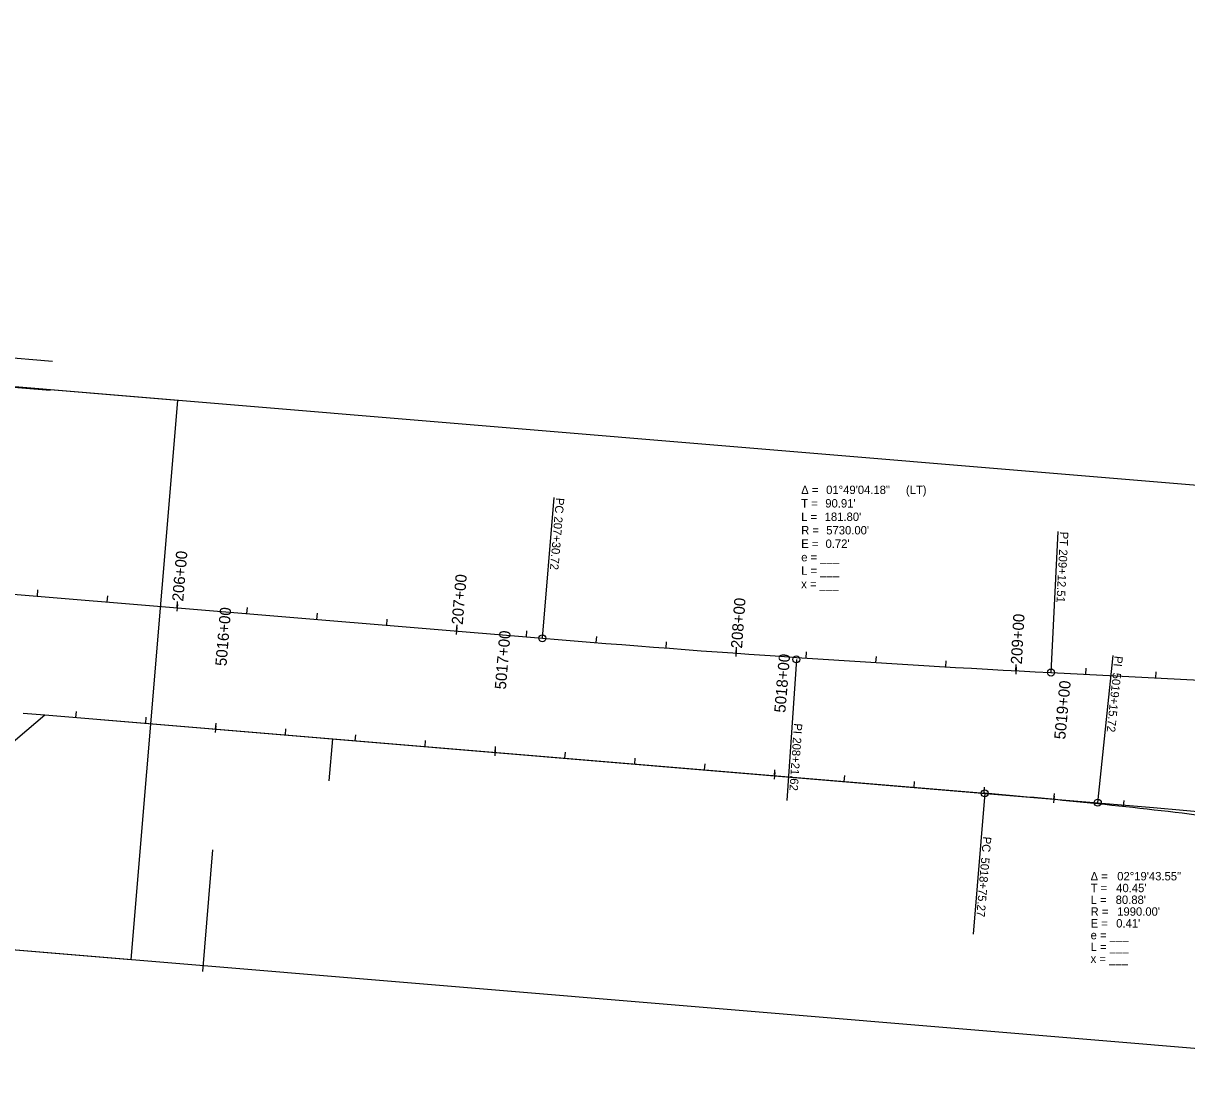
# Model space of a CAD drawing. Extents: x 20500393 to 20505339, y 7953466 to 7954298.
# Drawn here: x 20504244.5 to 20504659.4, y 7953509.6 to 7953886.7 of the extents above; entities that cross this region are included whole.
import ezdxf

# ---------------------------------------------------------------- set-up
doc = ezdxf.new("R2010")
doc.units = 0
for name, color, linetype in [('_CIVIL_CONSTRUCTION', 7, 'Continuous'), ('Alignment', 7, 'Continuous'), ('Draft_2', 7, 'Continuous'), ('Draft_3', 7, 'Continuous'), ('Draft_7', 7, 'Continuous'), ('NamedBoundary', 7, 'Continuous'), ('TextAlignment', 7, 'Continuous'), ('TextAlignmentLrg', 7, 'Continuous'), ('TextAlignmentSml', 7, 'Continuous'), ('Utility-Water - alignment', 7, 'Continuous')]:
    doc.layers.add(name, color=color, linetype=linetype)

msp = doc.modelspace()

# ---------------------------------------------------------------- linework, layer by layer
at = {"layer": '_CIVIL_CONSTRUCTION'}
for p, q in [((20502804.53, 7953803.04), (20504247.96, 7953682.58)), ((20502804.53, 7953803.04), (20504247.96, 7953682.58)), ((20504247.96, 7953682.58), (20504429.6, 7953667.42)), ((20504247.96, 7953682.58), (20504429.6, 7953667.42)), ((20504610.98, 7953655.19), (20505314.06, 7953618.94)), ((20504610.98, 7953655.19), (20505314.06, 7953618.94)), ((20504244.47, 7953640.72), (20504252.16, 7953640.08)), ((20504252.16, 7953640.08), (20504587.36, 7953612.12))]:
    msp.add_line(p, q, dxfattribs=at)
for centre, radius, start, end in [((20504906, 7959377.59), 5730, 265.230833, 267.04866), ((20504906, 7959377.59), 5730, 265.230833, 267.04866), ((20504421.91, 7951629.01), 1990, 82.90207, 85.23083)]:
    msp.add_arc(centre, radius, start, end, dxfattribs=at)
at = {"layer": 'Alignment'}
for p, q in [((20504244.47, 7953640.72), (20504252.16, 7953640.08)), ((20504244.47, 7953640.72), (20504252.16, 7953640.08)), ((20504252.16, 7953640.08), (20504587.36, 7953612.12)), ((20504252.16, 7953640.08), (20504587.36, 7953612.12))]:
    msp.add_line(p, q, dxfattribs=at)
msp.add_arc((20504421.91, 7951629.01), 1990, 82.90207, 85.23083, dxfattribs=at)
msp.add_arc((20504421.91, 7951629.01), 1990, 82.90207, 85.23083, dxfattribs=at)
at = {"layer": 'Draft_2'}
for p, q in [((20502811.52, 7953886.75), (20504254.94, 7953766.29)), ((20502810.65, 7953876.37), (20504254.08, 7953755.91))]:
    msp.add_line(p, q, dxfattribs=at)
at = {"layer": 'Draft_3'}
for p, q in [((20504244.47, 7953640.72), (20504252.16, 7953640.08)), ((20504244.47, 7953640.72), (20504252.16, 7953640.08)), ((20504311.95, 7953591.95), (20504308.33, 7953548.56))]:
    msp.add_line(p, q, dxfattribs=at)
at = {"layer": 'Draft_7'}
for p, q in [((20504207.89, 7953602.63), (20504252.16, 7953640.08)), ((20504252.16, 7953640.08), (20504647.49, 7953607.1)), ((20504647.49, 7953607.1), (20504687.32, 7953603.43))]:
    msp.add_line(p, q, dxfattribs=at)
at = {"layer": 'NamedBoundary'}
for points in [[(20503717.13, 7953800.83), (20503700.49, 7953601.52), (20504282.98, 7953552.91), (20504299.61, 7953752.22)], [(20504199.95, 7953760.54), (20504183.32, 7953561.23), (20504801.82, 7953509.62), (20504818.46, 7953708.92)]]:
    msp.add_lwpolyline(points, close=True, dxfattribs=at)
at = {"layer": 'TextAlignment'}
for p, q in [((20504429.6, 7953667.42), (20504433.79, 7953717.65)), ((20504433.79, 7953717.65), (20504433.79, 7953717.65)), ((20504610.98, 7953655.19), (20504613.57, 7953705.52)), ((20504613.57, 7953705.52), (20504613.57, 7953705.52)), ((20504627.67, 7953608.75), (20504633.13, 7953661.27)), ((20504633.13, 7953661.27), (20504633.13, 7953661.27)), ((20504520.19, 7953659.87), (20504516.8, 7953609.58)), ((20504587.36, 7953612.12), (20504583.17, 7953561.89)), ((20504516.8, 7953609.58), (20504516.8, 7953609.58)), ((20504583.17, 7953561.89), (20504583.17, 7953561.89))]:
    msp.add_line(p, q, dxfattribs=at)
for centre in [(20504429.6, 7953667.42), (20504520.19, 7953659.87), (20504610.98, 7953655.19), (20504587.36, 7953612.12), (20504627.67, 7953608.75)]:
    msp.add_circle(centre, 1.25, dxfattribs=at)
at = {"layer": 'TextAlignmentLrg'}
for p, q in [((20504299.33, 7953678.29), (20504299.52, 7953680.47)), ((20504398.99, 7953669.98), (20504399.17, 7953672.16)), ((20504498.68, 7953662.08), (20504498.83, 7953664.26)), ((20504598.48, 7953655.84), (20504598.6, 7953658.03)), ((20504313.04, 7953635), (20504313.23, 7953637.18)), ((20504412.7, 7953626.69), (20504412.88, 7953628.87)), ((20504512.35, 7953618.37), (20504512.53, 7953620.55)), ((20504611.99, 7953609.91), (20504612.2, 7953612.08))]:
    msp.add_line(p, q, dxfattribs=at)
at = {"layer": 'TextAlignmentSml'}
for p, q in [((20504249.51, 7953682.45), (20504249.69, 7953684.63)), ((20504274.42, 7953680.37), (20504274.6, 7953682.55)), ((20504299.44, 7953679.51), (20504299.23, 7953677.07)), ((20504324.25, 7953676.21), (20504324.43, 7953678.39)), ((20504349.16, 7953674.14), (20504349.34, 7953676.31)), ((20504374.08, 7953672.06), (20504374.26, 7953674.23)), ((20504399.09, 7953671.2), (20504398.89, 7953668.76)), ((20504423.9, 7953667.9), (20504424.08, 7953670.08)), ((20504448.82, 7953665.85), (20504448.99, 7953668.03)), ((20504473.74, 7953663.91), (20504473.91, 7953666.09)), ((20504498.76, 7953663.3), (20504498.59, 7953660.86)), ((20504523.62, 7953660.36), (20504523.76, 7953662.54)), ((20504548.56, 7953658.75), (20504548.7, 7953660.93)), ((20504573.52, 7953657.24), (20504573.65, 7953659.42)), ((20504598.55, 7953657.07), (20504598.41, 7953654.62)), ((20504623.45, 7953654.54), (20504623.56, 7953656.72)), ((20504648.41, 7953653.26), (20504648.52, 7953655.44)), ((20504263.22, 7953639.16), (20504263.4, 7953641.34)), ((20504288.13, 7953637.08), (20504288.31, 7953639.26)), ((20504313.15, 7953636.22), (20504312.94, 7953633.78)), ((20504337.96, 7953632.92), (20504338.14, 7953635.1)), ((20504362.87, 7953630.85), (20504363.05, 7953633.02)), ((20504387.78, 7953628.77), (20504387.97, 7953630.94)), ((20504412.8, 7953627.91), (20504412.6, 7953625.47)), ((20504437.61, 7953624.61), (20504437.79, 7953626.79)), ((20504462.53, 7953622.53), (20504462.71, 7953624.71)), ((20504487.44, 7953620.45), (20504487.62, 7953622.63)), ((20504512.45, 7953619.59), (20504512.25, 7953617.16)), ((20504537.27, 7953616.3), (20504537.45, 7953618.47)), ((20504562.18, 7953614.22), (20504562.36, 7953616.39)), ((20504587.09, 7953612.14), (20504587.27, 7953614.32)), ((20504612.11, 7953611.13), (20504611.88, 7953608.69)), ((20504636.86, 7953607.36), (20504637.1, 7953609.53))]:
    msp.add_line(p, q, dxfattribs=at)
at = {"layer": 'Utility-Water - alignment'}
msp.add_line((20504354.7, 7953631.53), (20504353.45, 7953616.58), dxfattribs=at)

# ---------------------------------------------------------------- texts
at = {"layer": 'TextAlignment'}
for s, p in [('Δ = ', (20504521.9, 7953718.85)), ('01°49\'04.18"', (20504530.79, 7953718.85)), (' (LT)', (20504558.13, 7953718.85)), ('T = ', (20504521.9, 7953714.05)), ("90.91'", (20504530.48, 7953714.05)), ('L = ', (20504521.9, 7953709.25)), ("181.80'", (20504530.26, 7953709.25)), ('R = ', (20504521.9, 7953704.45)), ("5730.00'", (20504530.83, 7953704.45)), ('E = ', (20504521.9, 7953699.65)), ("0.72'", (20504530.57, 7953699.65)), ('e = ___ ', (20504521.9, 7953694.85)), ('L = ___', (20504521.9, 7953690.05)), ('x = ___', (20504521.9, 7953685.25)), ('Δ = ', (20504625.1, 7953581.06)), ('02°19\'43.55"', (20504634.6, 7953581.06)), ('T = ', (20504625.1, 7953576.86)), ("40.45'", (20504634.23, 7953576.86)), ('L = ', (20504625.1, 7953572.66)), ("80.88'", (20504634.04, 7953572.66)), ('R = ', (20504625.1, 7953568.46)), ("1990.00'", (20504634.59, 7953568.46)), ('E = ', (20504625.1, 7953564.26)), ("0.41'", (20504634.23, 7953564.26)), ('e = ___ ', (20504625.1, 7953560.06)), ('L = ___', (20504625.1, 7953555.86)), ('x = ___', (20504625.1, 7953551.66))]:
    msp.add_text(s, height=3, dxfattribs=at).set_placement(p)
for s, rotation, p in [('PC', 265.2308, (20504434.45, 7953717.6)), ('207+30.72', 265.2308, (20504433.89, 7953710.95)), ('PT', 267.0487, (20504614.23, 7953705.49)), ('209+12.51', 267.0487, (20504613.9, 7953699.19)), ('PI ', 264.0665, (20504633.66, 7953661.22)), ('5019+15.72', 264.0665, (20504633.05, 7953655.27)), ('PI ', 266.1397, (20504519.32, 7953637.16)), ('208+21.62', 266.1397, (20504518.98, 7953632.16)), ('PC', 265.2308, (20504586.74, 7953596.78)), ('5018+75.27', 265.2308, (20504586.12, 7953589.34))]:
    msp.add_text(s, height=3, rotation=rotation, dxfattribs=at).set_placement(p)
at = {"layer": 'TextAlignmentSml'}
for s, rotation, p in [('206+00', 85.2308, (20504301.52, 7953680.44)), ('207+00', 85.2308, (20504401.18, 7953672.12)), ('208+00', 85.9236, (20504500.8, 7953663.7)), ('5016+00', 85.2308, (20504316.92, 7953657.37)), ('209+00', 86.9235, (20504600.6, 7953658.04)), ('5017+00', 85.2308, (20504416.57, 7953649.05)), ('5018+00', 85.2308, (20504516.23, 7953640.74)), ('5019+00', 84.5189, (20504616.05, 7953631.21))]:
    msp.add_text(s, height=4.008, rotation=rotation, dxfattribs=at).set_placement(p)

doc.saveas('drawing.dxf')
